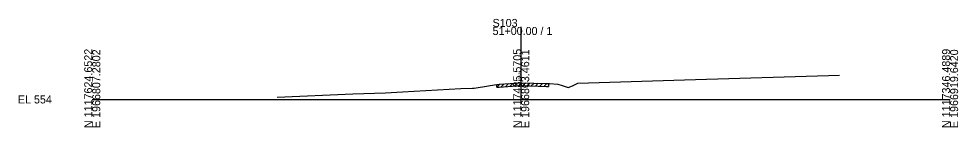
# Model space of a CAD drawing. Extents: x 974 to 1303, y 990 to 14518.
# Drawn here: x 974.3 to 1302.8, y 1490.3 to 1528.2 of the extents above; entities that cross this region are included whole.
import ezdxf

# ---------------------------------------------------------------- set-up
doc = ezdxf.new("R2010")
doc.units = 0
for name, color, linetype in [('Level 10', 7, 'Continuous'), ('Level 60', 7, 'Continuous'), ('Level 61', 7, 'Continuous'), ('Level 63', 7, 'Continuous')]:
    doc.layers.add(name, color=color, linetype=linetype)

msp = doc.modelspace()

# ---------------------------------------------------------------- linework, layer by layer
at = {"layer": 'Level 60'}
for p, q in [((1207.06, 1506.89), (1261.3, 1508.44)), ((1133.61, 1503.91), (1138.61, 1504.78)), ((1138.61, 1504.78), (1139.19, 1504.87)), ((1139.19, 1504.87), (1141.52, 1505.26)), ((1141.52, 1505.26), (1142.32, 1505.31)), ((1142.32, 1505.31), (1150.02, 1505.81)), ((1150.02, 1505.81), (1158.8, 1505.56)), ((1158.8, 1505.56), (1159.51, 1505.54)), ((1159.51, 1505.54), (1159.92, 1505.51)), ((1159.92, 1505.51), (1162.85, 1505.32)), ((1162.85, 1505.32), (1164.34, 1504.91)), ((1164.34, 1504.91), (1166.47, 1504.2)), ((1166.47, 1504.2), (1167.92, 1504.77)), ((1167.92, 1504.77), (1169.86, 1505.71)), ((1169.86, 1505.71), (1207.06, 1506.89)), ((1064.64, 1500.84), (1091.15, 1501.99)), ((1091.15, 1501.99), (1102.51, 1502.36)), ((1102.51, 1502.36), (1108.55, 1502.7)), ((1108.55, 1502.7), (1128.89, 1503.85)), ((1128.89, 1503.85), (1132.97, 1503.9)), ((1132.97, 1503.9), (1133.61, 1503.91))]:
    msp.add_line(p, q, dxfattribs=at)
at = {"layer": 'Level 61'}
for p, q in [((1141.52, 1504.26), (1142.59, 1505.33)), ((1141.52, 1504.26), (1141.52, 1505.26)), ((1142.32, 1504.31), (1150.02, 1504.81)), ((1143.02, 1504.36), (1144.09, 1505.43)), ((1144.52, 1504.45), (1145.59, 1505.52)), ((1146.02, 1504.55), (1147.09, 1505.62)), ((1147.52, 1504.65), (1148.59, 1505.72)), ((1149.02, 1504.75), (1150.08, 1505.81)), ((1150.02, 1504.81), (1158.8, 1504.56)), ((1150.52, 1504.8), (1151.49, 1505.77)), ((1152.02, 1504.75), (1152.99, 1505.73)), ((1153.52, 1504.71), (1154.49, 1505.68)), ((1155.02, 1504.67), (1155.99, 1505.64)), ((1156.52, 1504.62), (1157.49, 1505.6)), ((1158.02, 1504.58), (1158.99, 1505.55)), ((1159.51, 1505.54), (1159.51, 1504.54)), ((1141.52, 1504.26), (1142.32, 1504.31)), ((1141.52, 1504.26), (1141.52, 1504.26)), ((1158.8, 1504.56), (1159.51, 1504.54))]:
    msp.add_line(p, q, dxfattribs=at)
at = {"layer": 'Level 63'}
for p, q in [((1150, 1500), (1150, 1525.31)), ((1000, 1500), (1150, 1500)), ((1150, 1500), (1300, 1500))]:
    msp.add_line(p, q, dxfattribs=at)

# ---------------------------------------------------------------- texts
at = {"layer": 'Level 10'}
msp.add_text('559.81', height=0.9, rotation=90, dxfattribs=at).set_placement((1149.95, 1506.31))
at = {"layer": 'Level 63'}
for s, p in [('S103', (1140, 1525.31)), ('51+00.00 / 1', (1140, 1522.51)), ('EL 554', (974, 1498.6))]:
    msp.add_text(s, height=2.8, dxfattribs=at).set_placement(p)
for s, p in [('N 1117624.6522', (1000, 1490)), ('E 1966807.2802', (1002.8, 1490)), ('N 1117485.5705', (1150, 1490)), ('E 1966863.4611', (1152.8, 1490)), ('N 1117346.4889', (1300, 1490)), ('E 1966919.6420', (1302.8, 1490))]:
    msp.add_text(s, height=2.8, rotation=90, dxfattribs=at).set_placement(p)

doc.saveas('drawing.dxf')
